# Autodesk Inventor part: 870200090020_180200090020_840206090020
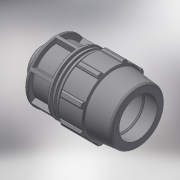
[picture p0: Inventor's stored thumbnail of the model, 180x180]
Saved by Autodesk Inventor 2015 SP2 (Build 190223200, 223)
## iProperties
Created: 2017-02
Part Number: 870200090020_180200090020_840206090020
Material: Generic
Description: PLASSON MALE ADAPTOR 90-2"
Document SubType Name: Modeling
Designer: KIM
Mass: 964.158 g
Surface Area: 1468.9 cm^2
Volume: 964.158 cm^3
Density: 1 g/cm^3
Appearance: Default
Author: KIM
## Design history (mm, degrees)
derived "87020.ipt"
feature "Solid1::87020.ipt"
tag "TaggingFeature1"
body "Solid1"
other parameters: "d4" = 32.28571, "d5" = 56.5, "d7" = 152, "d8" = 114, "d9" = 32.28571, "d11" = 6.45714, "d12" = 121.6, "d13" = 120 deg, "d14" = 117, "d15" = 6 deg, "d16" = 136.8, "d18" = 4.5, "d19" = 35 deg, "d20" = 17.5 deg, "d21" = 141.36, "d23" = 0, "d25" = 360 deg, "d27" = 3.04, "d34" = 7.6, "d36" = 0, "d42" = 56.5, "d43" = 4.56, "d46" = 2.7, "d49" = 169, "d51" = 226, "d52" = 26, "d53" = 1.8, "d55" = 360 deg, "d57" = 59.614, "d58" = 41.7298, "d59" = 45.2, "d61" = 134.064, "d62" = 5.77714, "d63" = 5.77714, "d66" = 11.55429, "E_" = 152, "H_" = 226, "l_" = 169, "l_2" = 26, "R_" = 59.614, "d60" = 28.88571
